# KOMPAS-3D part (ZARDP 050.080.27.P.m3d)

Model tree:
1. Булева операция:1
2. Булева операция:2
3. Булева операция:3
4. Булева операция:4
5. Булева операция:5
6. Булева операция:6
7. Булева операция:7
8. Булева операция:8
9. Булева операция:9
10. Булева операция:10
11. Булева операция:11
12. Булева операция:12
13. Булева операция:13
14. Булева операция:14
15. Булева операция:15
16. Булева операция:16
17. Булева операция:17
18. Булева операция:18
19. Булева операция:19
20. Булева операция:20
21. Булева операция:21
22. Булева операция:22

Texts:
  ООО ИК Энерпред-Ярдос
